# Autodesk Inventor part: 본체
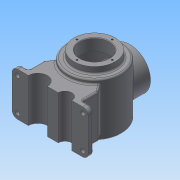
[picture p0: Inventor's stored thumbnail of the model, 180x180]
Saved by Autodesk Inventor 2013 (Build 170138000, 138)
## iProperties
Created: 2018-08
Part Number: 본체
Material: 일반
Document SubType Name: Modeling
Designer: Administrator
Density: 1 g/cm^3
Author: Administrator
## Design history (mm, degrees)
sketch "스케치1"
  geometry: L1 (0, 0)-(50, 0); L2 (50, 0)-(50, -96.671); L3 (0, -108)-(0, 0); A1 r 116 centre (0, 8) between (0, -108) and (50, -96.671); A2 r 116 centre (0, 8) between (0, -108) and (50, -96.671)
  constraints: 6 end point, 4 point on circle, 2 centre point, 1 horizontal, 1 parallel, 1 perpendicular, 1 point on line
revolve "회전1" sketch "스케치1" stored, may be unused: angle "d3" = 90 deg
sketch "스케치2"
  geometry: C1 r 50 at (0, 0) reference; C2 r 38 at (0, 0)
  constraints: 1 centre point, 1 coincident
  dimensions: "d4" = 76 diameter of C2
extrude "돌출1" join sketch "스케치2" distance "d5" = 12; taper "d6" = 0 deg
sketch "스케치3"
  geometry: C1 r 38 at (0, 0) reference; C2 r 27 at (0, 0)
  constraints: 1 centre point, 1 coincident
  dimensions: "d7" = 54 diameter of C2
extrude "돌출2" cut sketch "스케치3" distance "d8" = 22; taper "d9" = 0 deg
sketch "스케치4"
  geometry: L1 (-27, -10)-(27, -10) reference; L2 (0, -10)-(40, -10); L3 (40, -10)-(40, -90.163); L4 (0, -98)-(0, -10); A1 r 116 centre (0, 8) between (-50, -96.671) and (50, -96.671) reference; A2 r 106 centre (0, 8) between (0, -98) and (40, -90.163); 1 further point
  constraints: 6 end point, 2 point on circle, 1 centre point, 1 horizontal, 1 midpoint, 1 parallel, 1 perpendicular
  dimensions: "d10" = 10 radial gap between concentric circles of A1 A2; "d11" = 40 distance between parallel lines of L4 L3
revolve "회전2" sketch "스케치4" stored, may be unused: angle "d12" = 90 deg
node "작업 평면1"
sketch "스케치5"
  geometry: L1 (38, 12)-(-38, 12) reference; L2 (-50, 0)-(50, 0) reference; C1 r 38 at (0, -50); 1 further point
  constraints: 1 centre point
  dimensions: "d14" = 76 diameter of C1; "d15" = 50 distance from line of C1.centre L2
extrude "돌출3" join sketch "스케치5" stored distance "d16" = 50 (= d15); taper "d17" = 0 deg
sketch "스케치6"
  geometry: C1 r 38 at (0, 0) reference; C2 r 27 at (0, 0); 1 further point
  constraints: 1 centre point, 1 coincident
  dimensions: "d18" = 54 diameter of C2
extrude "돌출4" cut sketch "스케치6" stored distance "d19" = 22; taper "d20" = 0 deg
sketch "스케치7"
  geometry: C1 r 27 at (0, 0) reference; 2 further points
  dimensions: "d21" = 32.5 distance of C1.centre point (0, 32.5)
hole "구멍1" sketch "스케치7" at (0, 32.5) diameter "d22" = 3.242; stored, may be unused: countersink angle "d26" = 90 deg, drill point angle "d28" = 118 deg; dims "d23" = 8, "d24" = 4, "d25" = 2, "d27" = 10
sketch "스케치8"
  geometry: C1 r 27 at (0, 0) reference; 1 further point
  dimensions: "d32" = 32.5 distance of C1.centre point (0, 32.5)
hole "구멍2" sketch "스케치8" at (0, 32.5) diameter "d33" = 3.242; stored, may be unused: countersink angle "d37" = 90 deg, drill point angle "d39" = 118 deg; dims "d34" = 8, "d35" = 4, "d36" = 2, "d38" = 10
node "작업 평면2"
sketch "스케치9"
  geometry: L1 (-50, 0)-(50, 0) reference; L2 (-70, -8)-(70, -8); L3 (70, -8)-(70, -88); L4 (70, -88)-(-70, -88); L5 (-70, -88)-(-70, -8); 1 further point
  constraints: 8 end point, 2 parallel, 1 horizontal, 1 perpendicular
  dimensions: "d44" = 8 distance between parallel lines of L2 L1; "d45" = 140 distance between parallel lines of L5 L3; "d46" = 70 distance from line of point (0, 0) L5; "d47" = 80 distance between parallel lines of L2 L4
extrude "돌출5" join sketch "스케치9" distance "d48" = 10; taper "d49" = 0 deg
sketch "스케치11"
  geometry: L1 (0, 10)-(140, 10) reference; L2 (140, 10)-(109.62, 53.386); L3 (140, 10)-(192.965, 10); L4 (109.62, 53.386)-(70, 33.165); L5 (70, 33.165)-(70, 10); 1 further point
  constraints: 8 end point, 1 equal length, 1 horizontal, 1 midpoint
  dimensions: "d52" = 125 deg angle of L3 L2
feature "리브1" sketch "스케치11" dims "d53" = 1, "d54" = 80, "d55" = 0, "d56" = 0, "d57" = 1, "d58" = 1
sketch "스케치12"
  geometry: L1 (140, 10)-(120, 10); L2 (120, 10)-(120, 53.415); L3 (120, 53.415)-(140, 53.415); L4 (140, 53.415)-(140, 10)
  constraints: 8 end point, 2 parallel, 1 horizontal, 1 perpendicular
  dimensions: "d59" = 20 distance of L2.end L3.end
extrude "돌출6" cut sketch "스케치12" stored distance "d60" = 10; taper "d61" = 0 deg
sketch "스케치13"
  geometry: L1 (70, -8)-(-70, -8) reference; L2 (-70, -88)-(70, -88) reference; L3 (70, -88)-(70, -8) reference; C1 r 4 at (60, -18); C2 r 4 at (60, -78); 1 further point
  constraints: 2 centre point
  dimensions: "d62" = 8 diameter of C1; "d63" = 8 diameter of C2; "d64" = 10 distance from line of L1 C1.centre; "d65" = 10 distance from line of L3 C1.centre; "d66" = 10 distance from line of L3 C2.centre; "d67" = 10 distance from line of L2 C2.centre
extrude "돌출7" cut sketch "스케치13" distance "d68" = 10; taper "d69" = 0 deg
sketch "스케치14"
  geometry: L1 (140, 0)-(0, 0) reference; L2 (0, 0)-(140, 0) reference; C1 r 12.5 at (42.5, 0); C2 r 17.5 at (92.5, 0); A1 r 50 centre (70, 82) between (29.696, 52.41) and (110.304, 52.41) reference; A2 r 50 centre (70, 82) between (110.304, 52.41) and (29.696, 52.41) reference
  constraints: 2 centre point, 1 point on line
  dimensions: "d70" = 25 diameter of C1; "d71" = 35 diameter of C2; "d72" = 27.5 horizontal distance of C1.centre A1.centre; "d73" = 22.5 horizontal distance of A1.centre C2.centre
extrude "돌출8" cut sketch "스케치14" stored distance "d74" = 10; taper "d75" = 0 deg
chamfer "모따기1" distance "d76" = 1; stored, may be unused: second distance "d77" = 2, angle "d78" = 45 deg
fillet "모깎기1" dims "d79" = 3
fillet "모깎기2" dims "d80" = 3
chamfer "모따기2" distance "d81" = 1; stored, may be unused: second distance "d82" = 2, angle "d83" = 45 deg
fillet "모깎기3" dims "d84" = 3
fillet "모깎기4" dims "d85" = 10
fillet "모깎기5" dims "d86" = 3
fillet "모깎기6" dims "d87" = 3
fillet "모깎기7" dims "d88" = 3
node "작업 평면3"
sketch "스케치15"
  geometry: C1 r 32.5 at (0, 0); 1 further point
  constraints: 1 centre point, 1 coincident, 1 other
  dimensions: "d90" = 65 diameter of C1
feature "엠보싱1" sketch "스케치15" dims "d91" = 0.5, "d92" = 0
node "솔리드1"
pattern_circular "원형 패턴1" dims angle "d30" = 360 deg
pattern_circular "원형 패턴2" dims angle "d41" = 360 deg
mirror "대칭1"
mirror "대칭2"
mirror "대칭3"
other parameters: "d2" = 232, "d13" = 65, "d43" = -82, "d89" = -108
